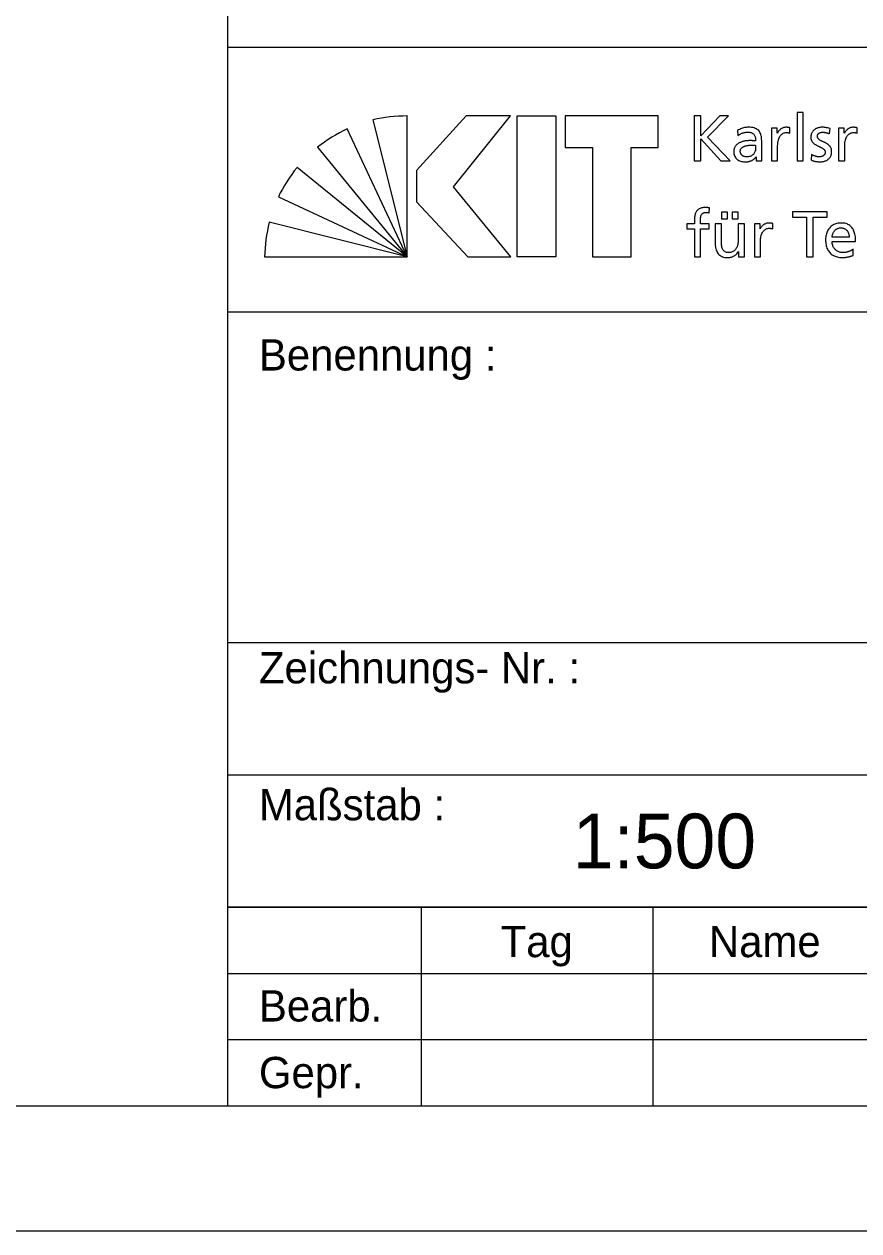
# Model space of a CAD drawing. Extents: x 0 to 210, y 0 to 148.
# Drawn here: x 157.5 to 184.16, y 0 to 38.57 of the extents above; entities that cross this region are included whole.
import ezdxf

# ---------------------------------------------------------------- set-up
doc = ezdxf.new("R2010")
doc.units = 0
doc.layers.add('90_Plankopf', color=7, linetype='Continuous')

msp = doc.modelspace()

# ---------------------------------------------------------------- linework, layer by layer
at = {"layer": '90_Plankopf'}
for p, q in [((164.001, 37.84), (164.001, 44.185)), ((164.001, 37.84), (206, 37.84)), ((168.637, 35.511), (169.74, 31.138)), ((169.74, 31.138), (169.74, 35.637)), ((178.905, 35.638), (178.905, 34.198)), ((169.74, 31.138), (167.817, 35.221)), ((180.29, 35.176), (180.3, 35.011)), ((181.963, 35.087), (181.963, 35.261)), ((183.228, 35.065), (183.245, 35.234)), ((184.106, 35.087), (184.106, 35.261)), ((181.059, 34.404), (181.059, 34.84)), ((166.872, 34.638), (169.74, 31.138)), ((180.865, 34.699), (180.865, 34.606)), ((182.649, 34.404), (182.638, 34.231)), ((169.74, 31.138), (166.217, 33.988)), ((178.905, 34.198), (179.111, 34.198)), ((179.753, 34.198), (180.054, 34.198)), ((165.62, 33.052), (169.74, 31.138)), ((179.387, 32.541), (179.395, 32.698)), ((169.74, 31.138), (165.329, 32.239)), ((181.413, 32.027), (181.413, 32.201)), ((183.853, 31.765), (183.308, 31.765)), ((183.308, 31.621), (184.059, 31.621)), ((183.979, 31.182), (183.979, 31.375)), ((165.182, 31.138), (169.74, 31.138)), ((164.001, 29.38), (206, 29.38)), ((164.001, 18.805), (206, 18.805)), ((164.001, 14.575), (206, 14.575)), ((164.001, 10.345), (206, 10.345)), ((164.001, 10.345), (206, 10.345)), ((164.001, 10.345), (206, 10.345)), ((164.001, 10.345), (206, 10.345)), ((164.001, 4), (164.001, 10.345)), ((170.177, 10.345), (170.177, 4)), ((177.589, 4), (177.589, 10.345)), ((164.001, 8.23), (185, 8.23)), ((164.001, 6.115), (185, 6.115)), ((164.001, 4), (206, 4)), ((164.001, 4), (206, 4))]:
    msp.add_line(p, q, dxfattribs=at)
for points in [[(0, 0), (210, 0), (210, 148.5), (0, 148.5)], [(4, 4), (206, 4), (206, 144.5), (4, 144.5)], [(173.033, 35.638), (171.618, 35.638), (170.036, 33.894), (170.036, 32.891), (171.669, 31.138), (173.042, 31.138), (171.211, 33.376)], [(174.485, 35.638), (174.485, 31.138), (173.251, 31.138), (173.251, 35.638)], [(174.781, 35.638), (174.781, 34.625), (175.651, 34.625), (175.651, 31.138), (176.885, 31.138), (176.885, 34.625), (177.755, 34.625), (177.755, 35.638)]]:
    msp.add_lwpolyline(points, close=True, dxfattribs=at)
for points in [[(164.001, 10.345), (164.001, 37.84)], [(180.054, 34.198), (179.324, 34.957), (180, 35.638), (179.726, 35.638), (179.111, 35.005), (179.111, 35.638), (178.905, 35.638)], [(182.19, 34.198), (182.384, 34.198), (182.384, 35.745), (182.19, 35.745), (182.19, 34.198)], [(181.561, 35.087), (181.557, 35.087), (181.557, 35.25), (181.375, 35.25), (181.375, 34.198), (181.569, 34.198), (181.569, 34.677)], [(183.703, 35.087), (183.699, 35.087), (183.699, 35.25), (183.518, 35.25), (183.518, 34.198), (183.712, 34.198), (183.712, 34.677)], [(179.111, 34.198), (179.111, 34.904), (179.753, 34.198)], [(180.882, 34.334), (180.886, 34.334), (180.886, 34.198), (181.067, 34.198)], [(179.777, 32.558), (179.777, 32.351), (179.971, 32.351), (179.971, 32.558), (179.777, 32.558)], [(180.115, 32.558), (180.115, 32.351), (180.309, 32.351), (180.309, 32.558), (180.115, 32.558)], [(182.495, 31.138), (182.701, 31.138), (182.701, 32.397), (183.149, 32.397), (183.149, 32.578), (182.047, 32.578), (182.047, 32.397), (182.495, 32.397), (182.495, 31.138)], [(178.912, 32.288), (178.912, 32.191), (178.665, 32.191), (178.665, 32.034), (178.912, 32.034), (178.912, 31.138), (179.106, 31.138), (179.106, 32.034), (179.385, 32.034), (179.385, 32.191), (179.106, 32.191), (179.106, 32.304)], [(179.771, 31.646), (179.771, 32.191), (179.577, 32.191), (179.577, 31.565)], [(180.507, 31.138), (180.507, 32.191), (180.313, 32.191), (180.313, 31.704)], [(181.011, 32.027), (181.007, 32.027), (181.007, 32.191), (180.825, 32.191), (180.825, 31.138), (181.019, 31.138), (181.019, 31.617)], [(180.316, 31.305), (180.32, 31.305), (180.32, 31.138), (180.507, 31.138)], [(206, 10.345), (164.001, 10.345)], [(164.001, 10.345), (164.001, 10.345)], [(164.001, 4), (206, 4)]]:
    msp.add_lwpolyline(points, dxfattribs=at)
for centre, start, end in [((169.724, 30.873), 89.8053, 103.1895), ((169.831, 30.904), 115.0126, 128.3968), ((169.908, 30.976), 140.7898, 154.174), ((169.946, 31.064), 165.7222, 179.1064)]:
    msp.add_arc(centre, 4.764, start, end, dxfattribs=at)
for points in [[(181.059, 34.84), (181.06, 34.935), (181.045, 35.015), (181.017, 35.08), (180.988, 35.145), (180.942, 35.193), (180.88, 35.226), (180.817, 35.258), (180.736, 35.275), (180.636, 35.275), (180.569, 35.275), (180.507, 35.265), (180.449, 35.247), (180.391, 35.229), (180.338, 35.206), (180.29, 35.176)], [(180.3, 35.011), (180.326, 35.033), (180.356, 35.052), (180.39, 35.068), (180.423, 35.084), (180.458, 35.096), (180.495, 35.105), (180.532, 35.114), (180.568, 35.118), (180.605, 35.118), (180.67, 35.118), (180.721, 35.108), (180.759, 35.088), (180.797, 35.067), (180.824, 35.036), (180.841, 34.996), (180.858, 34.955), (180.865, 34.904), (180.865, 34.844)], [(181.963, 35.261), (181.95, 35.263), (181.937, 35.266), (181.925, 35.268), (181.912, 35.27), (181.899, 35.272), (181.885, 35.273), (181.871, 35.274), (181.854, 35.275), (181.835, 35.275), (181.798, 35.275), (181.761, 35.267), (181.726, 35.251), (181.691, 35.235), (181.659, 35.213), (181.63, 35.184), (181.601, 35.156), (181.578, 35.124), (181.561, 35.087)], [(181.569, 34.677), (181.569, 34.765), (181.581, 34.841), (181.605, 34.905), (181.629, 34.969), (181.662, 35.019), (181.705, 35.053), (181.747, 35.088), (181.798, 35.105), (181.856, 35.106), (181.873, 35.106), (181.89, 35.105), (181.909, 35.102), (181.927, 35.099), (181.945, 35.094), (181.963, 35.087)], [(183.245, 35.234), (183.207, 35.245), (183.169, 35.255), (183.13, 35.263), (183.091, 35.271), (183.049, 35.275), (183.004, 35.275), (182.951, 35.275), (182.903, 35.268), (182.858, 35.255), (182.813, 35.242), (182.774, 35.222), (182.74, 35.195), (182.706, 35.168), (182.68, 35.135), (182.661, 35.094), (182.642, 35.053), (182.632, 35.006), (182.632, 34.951), (182.632, 34.909), (182.641, 34.873), (182.658, 34.842), (182.674, 34.811), (182.695, 34.785), (182.723, 34.762), (182.75, 34.74), (182.779, 34.72), (182.812, 34.702), (182.844, 34.685), (182.876, 34.669), (182.909, 34.654), (182.941, 34.638), (182.971, 34.622), (182.998, 34.606), (183.025, 34.59), (183.047, 34.572), (183.063, 34.551), (183.079, 34.531), (183.088, 34.508), (183.088, 34.481), (183.088, 34.452), (183.082, 34.429), (183.07, 34.409), (183.058, 34.39), (183.042, 34.374), (183.022, 34.363), (183.003, 34.351), (182.982, 34.343), (182.959, 34.338), (182.935, 34.332), (182.912, 34.33), (182.89, 34.33), (182.871, 34.33), (182.847, 34.333), (182.82, 34.338), (182.792, 34.344), (182.763, 34.352), (182.733, 34.363), (182.703, 34.374), (182.675, 34.388), (182.649, 34.404)], [(182.638, 34.231), (182.683, 34.208), (182.73, 34.192), (182.779, 34.184), (182.828, 34.176), (182.877, 34.172), (182.927, 34.173), (182.975, 34.173), (183.02, 34.18), (183.064, 34.193), (183.107, 34.206), (183.147, 34.226), (183.181, 34.253), (183.216, 34.28), (183.243, 34.314), (183.264, 34.355), (183.284, 34.396), (183.294, 34.445), (183.295, 34.501), (183.294, 34.549), (183.286, 34.59), (183.269, 34.623), (183.253, 34.656), (183.231, 34.685), (183.204, 34.708), (183.177, 34.731), (183.147, 34.751), (183.115, 34.767), (183.083, 34.784), (183.05, 34.799), (183.018, 34.813), (182.986, 34.828), (182.956, 34.843), (182.929, 34.858), (182.902, 34.874), (182.88, 34.892), (182.864, 34.913), (182.847, 34.934), (182.839, 34.96), (182.838, 34.99), (182.839, 35.019), (182.848, 35.043), (182.865, 35.062), (182.882, 35.081), (182.904, 35.095), (182.932, 35.104), (182.96, 35.114), (182.991, 35.118), (183.024, 35.118), (183.036, 35.118), (183.051, 35.116), (183.069, 35.114), (183.088, 35.111), (183.107, 35.106), (183.127, 35.101), (183.148, 35.096), (183.167, 35.091), (183.185, 35.084), (183.203, 35.078), (183.217, 35.071), (183.228, 35.065)], [(184.106, 35.261), (184.092, 35.263), (184.079, 35.266), (184.067, 35.268), (184.055, 35.27), (184.041, 35.272), (184.027, 35.273), (184.013, 35.274), (183.997, 35.275), (183.978, 35.275), (183.94, 35.275), (183.904, 35.267), (183.868, 35.251), (183.833, 35.235), (183.801, 35.213), (183.773, 35.184), (183.744, 35.156), (183.721, 35.124), (183.703, 35.087)], [(183.712, 34.677), (183.712, 34.765), (183.724, 34.841), (183.747, 34.905), (183.771, 34.969), (183.804, 35.019), (183.847, 35.053), (183.89, 35.088), (183.94, 35.105), (183.998, 35.106), (184.015, 35.106), (184.033, 35.105), (184.051, 35.102), (184.07, 35.099), (184.088, 35.094), (184.106, 35.087)], [(180.865, 34.844), (180.84, 34.845), (180.817, 34.846), (180.795, 34.846), (180.773, 34.847), (180.751, 34.848), (180.729, 34.848), (180.708, 34.848), (180.684, 34.848), (180.659, 34.848), (180.618, 34.848), (180.576, 34.844), (180.531, 34.837), (180.487, 34.83), (180.443, 34.818), (180.4, 34.802), (180.358, 34.786), (180.319, 34.764), (180.284, 34.737), (180.25, 34.711), (180.222, 34.678), (180.201, 34.639), (180.181, 34.6), (180.171, 34.554), (180.17, 34.501), (180.171, 34.425), (180.187, 34.363), (180.219, 34.314), (180.252, 34.266), (180.297, 34.23), (180.355, 34.207), (180.413, 34.184), (180.479, 34.173), (180.556, 34.173), (180.6, 34.173), (180.64, 34.179), (180.675, 34.189), (180.71, 34.2), (180.741, 34.213), (180.768, 34.229), (180.795, 34.246), (180.818, 34.264), (180.837, 34.282), (180.855, 34.3), (180.87, 34.317), (180.882, 34.334)], [(180.865, 34.606), (180.865, 34.554), (180.854, 34.506), (180.832, 34.465), (180.81, 34.423), (180.777, 34.391), (180.733, 34.367), (180.69, 34.343), (180.636, 34.33), (180.572, 34.33), (180.55, 34.33), (180.527, 34.334), (180.504, 34.341), (180.481, 34.348), (180.46, 34.359), (180.441, 34.374), (180.422, 34.388), (180.406, 34.406), (180.394, 34.427), (180.383, 34.449), (180.377, 34.473), (180.376, 34.501), (180.377, 34.538), (180.386, 34.569), (180.404, 34.594), (180.422, 34.618), (180.446, 34.638), (180.475, 34.652), (180.503, 34.667), (180.534, 34.678), (180.567, 34.686), (180.6, 34.693), (180.632, 34.698), (180.663, 34.7), (180.694, 34.703), (180.72, 34.704), (180.741, 34.703), (180.762, 34.703), (180.783, 34.703), (180.803, 34.701), (180.824, 34.7), (180.845, 34.7), (180.865, 34.699)], [(181.067, 34.198), (181.066, 34.208), (181.065, 34.222), (181.063, 34.238), (181.062, 34.256), (181.061, 34.278), (181.061, 34.305), (181.06, 34.331), (181.059, 34.365), (181.059, 34.404)], [(179.395, 32.698), (179.375, 32.701), (179.355, 32.704), (179.334, 32.707), (179.312, 32.709), (179.29, 32.711), (179.265, 32.711), (179.194, 32.71), (179.135, 32.7), (179.089, 32.681), (179.043, 32.661), (179.007, 32.632), (178.981, 32.595), (178.955, 32.558), (178.937, 32.513), (178.927, 32.461), (178.917, 32.41), (178.912, 32.352), (178.912, 32.288)], [(179.106, 32.304), (179.106, 32.34), (179.108, 32.373), (179.112, 32.403), (179.116, 32.433), (179.125, 32.46), (179.137, 32.482), (179.15, 32.505), (179.169, 32.522), (179.194, 32.535), (179.219, 32.547), (179.252, 32.554), (179.294, 32.554), (179.311, 32.554), (179.328, 32.553), (179.344, 32.551), (179.361, 32.548), (179.375, 32.545), (179.387, 32.541)], [(181.413, 32.201), (181.4, 32.204), (181.387, 32.206), (181.375, 32.208), (181.363, 32.21), (181.349, 32.212), (181.335, 32.213), (181.321, 32.215), (181.304, 32.215), (181.286, 32.215), (181.248, 32.215), (181.212, 32.207), (181.176, 32.191), (181.141, 32.175), (181.109, 32.153), (181.081, 32.125), (181.052, 32.097), (181.029, 32.064), (181.011, 32.027)], [(181.019, 31.617), (181.02, 31.705), (181.032, 31.782), (181.055, 31.846), (181.079, 31.91), (181.112, 31.959), (181.155, 31.993), (181.198, 32.028), (181.248, 32.046), (181.306, 32.046), (181.323, 32.046), (181.341, 32.045), (181.359, 32.042), (181.378, 32.04), (181.396, 32.035), (181.413, 32.027)], [(184.059, 31.621), (184.06, 31.706), (184.052, 31.785), (184.036, 31.857), (184.02, 31.929), (183.995, 31.991), (183.959, 32.045), (183.923, 32.099), (183.875, 32.14), (183.815, 32.17), (183.756, 32.2), (183.682, 32.215), (183.595, 32.215), (183.52, 32.215), (183.453, 32.202), (183.392, 32.176), (183.332, 32.15), (183.28, 32.114), (183.237, 32.066), (183.194, 32.019), (183.16, 31.963), (183.137, 31.897), (183.114, 31.833), (183.102, 31.761), (183.102, 31.683), (183.102, 31.597), (183.113, 31.519), (183.134, 31.449), (183.156, 31.38), (183.19, 31.32), (183.234, 31.27), (183.279, 31.22), (183.335, 31.181), (183.404, 31.154), (183.473, 31.127), (183.553, 31.114), (183.647, 31.113), (183.704, 31.114), (183.753, 31.118), (183.793, 31.125), (183.834, 31.133), (183.869, 31.142), (183.898, 31.152), (183.928, 31.162), (183.954, 31.172), (183.979, 31.182)], [(183.308, 31.765), (183.312, 31.8), (183.32, 31.834), (183.332, 31.869), (183.344, 31.903), (183.361, 31.934), (183.384, 31.963), (183.406, 31.992), (183.434, 32.015), (183.469, 32.032), (183.503, 32.049), (183.543, 32.058), (183.591, 32.058), (183.633, 32.058), (183.67, 32.051), (183.702, 32.035), (183.735, 32.02), (183.762, 31.999), (183.785, 31.972), (183.807, 31.946), (183.824, 31.914), (183.835, 31.879), (183.847, 31.844), (183.853, 31.806), (183.853, 31.765)], [(180.313, 31.704), (180.313, 31.639), (180.307, 31.581), (180.295, 31.528), (180.282, 31.475), (180.263, 31.429), (180.236, 31.391), (180.21, 31.352), (180.177, 31.323), (180.137, 31.302), (180.096, 31.281), (180.049, 31.271), (179.994, 31.27), (179.938, 31.274), (179.893, 31.289), (179.861, 31.318), (179.828, 31.346), (179.805, 31.387), (179.791, 31.442), (179.777, 31.496), (179.771, 31.564), (179.771, 31.646)], [(179.577, 31.565), (179.577, 31.471), (179.591, 31.39), (179.618, 31.323), (179.646, 31.255), (179.69, 31.204), (179.748, 31.168), (179.806, 31.132), (179.88, 31.114), (179.971, 31.113), (180.02, 31.114), (180.068, 31.121), (180.113, 31.136), (180.158, 31.152), (180.198, 31.174), (180.233, 31.202), (180.268, 31.231), (180.296, 31.265), (180.316, 31.305)], [(183.979, 31.375), (183.967, 31.366), (183.949, 31.355), (183.926, 31.342), (183.903, 31.33), (183.877, 31.319), (183.847, 31.308), (183.817, 31.297), (183.786, 31.288), (183.753, 31.281), (183.72, 31.274), (183.687, 31.271), (183.655, 31.27), (183.608, 31.271), (183.565, 31.279), (183.523, 31.296), (183.482, 31.313), (183.445, 31.337), (183.413, 31.368), (183.38, 31.399), (183.355, 31.435), (183.336, 31.478), (183.318, 31.521), (183.309, 31.569), (183.308, 31.621)]]:
    msp.add_open_spline(points, degree=3, dxfattribs=at)

# ---------------------------------------------------------------- texts
for s, height, p in [('Benennung :', 1, (165, 27.5)), ('Zeichnungs- Nr. :', 1, (165, 17.5)), ('Maßstab :', 1, (165, 13.125)), ('1:500   ', 1.75, (175.024, 11.587)), ('Tag', 1, (172.721, 8.75)), ('Name', 1, (179.375, 8.75)), ('Bearb.', 1, (165, 6.692)), ('Gepr.', 1, (165, 4.561))]:
    msp.add_text(s, height=height, dxfattribs=at).set_placement(p)

doc.saveas('drawing.dxf')
